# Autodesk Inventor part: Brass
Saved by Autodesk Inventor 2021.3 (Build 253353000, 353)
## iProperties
Created: 2024-03
Part Number: Brass
Material: Generic
Document SubType Name: Modeling
Designer: AdminForWorker
Density: 1 g/cm^3
Appearance: Default
Title: Brass
Author: AdminForWorker
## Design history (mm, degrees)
feature "Brass"
body "Solid1"
